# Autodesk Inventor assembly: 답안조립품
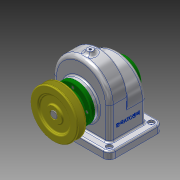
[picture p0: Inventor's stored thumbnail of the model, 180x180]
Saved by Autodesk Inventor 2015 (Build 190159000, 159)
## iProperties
Created: 2017-11
Part Number: 답안조립품
Document SubType Name: Assembly
Designer: SCD-A12
Author: SCD-A12
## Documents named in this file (14)
- C:\Users\SCD-A12\Desktop\471108V1029\답안조립품.iam
- C:\Users\SCD-A12\Desktop\471108V1029\본체.ipt
- C:\Users\SCD-A12\Desktop\471108V1029\V-벨트풀리.ipt
- C:\Users\SCD-A12\Desktop\471108V1029\뒤커버.ipt
- C:\Users\SCD-A12\Desktop\471108V1029\멈춤나사 - M4 x 10.ipt
- 멈춤나사 - M4 x 10.ipt
- C:\Users\SCD-A12\Desktop\471108V1029\베어링 6002.ipt
- C:\Users\SCD-A12\Desktop\471108V1029\볼트 M3 x 8.ipt
- C:\Users\SCD-A12\Desktop\471108V1029\스퍼기어.ipt
- C:\Users\SCD-A12\Desktop\471108V1029\앞커버.ipt
- C:\Users\SCD-A12\Desktop\471108V1029\오일 실 15 30 7.ipt
- C:\Users\SCD-A12\Desktop\471108V1029\축.ipt
- C:\Users\SCD-A12\Desktop\471108V1029\키 - 5 x 5 x 18.ipt
- C:\Users\SCD-A12\Desktop\471108V1029\키 - 6 x 6 x 22.ipt
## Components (1 placed, 1 different names)
1. V-벨트풀리:1
